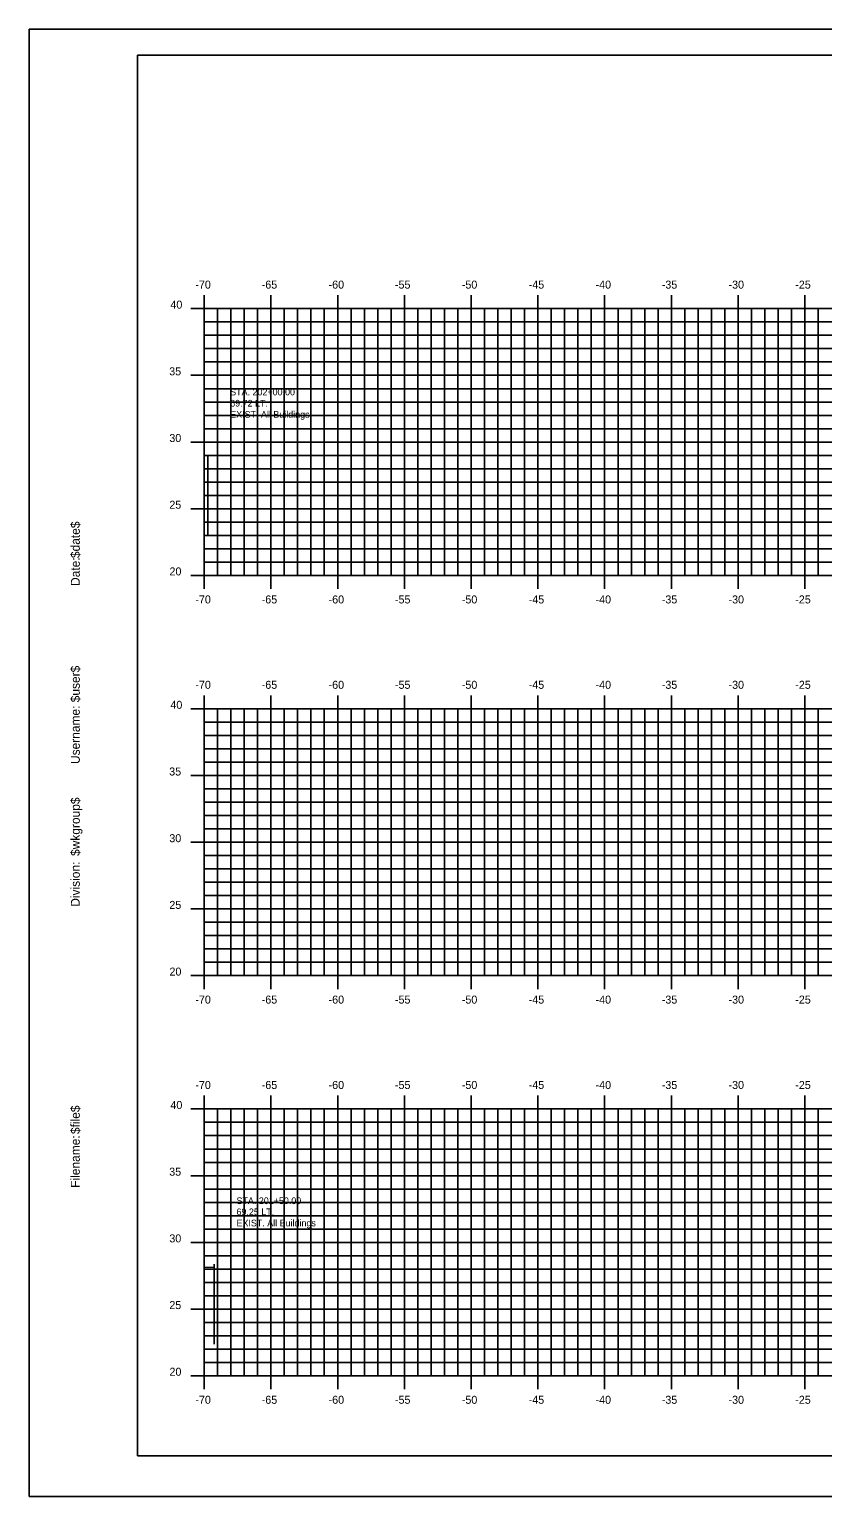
# Model space of a CAD drawing. Extents: x 1023905 to 1024075, y 394697 to 394807.
# Drawn here: x 1023904.6 to 1023964, y 394696.5 to 394806.5 of the extents above; entities that cross this region are included whole.
import ezdxf

# ---------------------------------------------------------------- set-up
doc = ezdxf.new("R2010")
doc.units = 0
for name, color, linetype in [('BORDER', 7, 'Continuous'), ('D_Text_Monospaced', 7, 'Continuous'), ('H_V ANNOTATION', 7, 'Continuous'), ('MAJOR', 7, 'Continuous'), ('MINOR', 7, 'Continuous'), ('PLOT BOUNDARY', 7, 'Continuous'), ('S_Roadway_Centerline', 7, 'Continuous'), ('S_Utilities_UG_Sanitary_Sewer', 7, 'Continuous')]:
    doc.layers.add(name, color=color, linetype=linetype)

msp = doc.modelspace()

# ---------------------------------------------------------------- linework, layer by layer
at = {"layer": 'BORDER'}
for p, q in [((1024072.67, 394804.61), (1023912.67, 394804.61)), ((1023912.67, 394804.61), (1023912.67, 394699.61)), ((1023912.67, 394699.61), (1024072.67, 394699.61))]:
    msp.add_line(p, q, dxfattribs=at)
at = {"layer": 'MAJOR'}
for p, q in [((1023916.66, 394785.61), (1023917.67, 394785.61)), ((1023917.67, 394786.61), (1023917.67, 394785.61)), ((1023917.67, 394785.61), (1024057.67, 394785.61)), ((1023917.67, 394765.61), (1023917.67, 394785.61)), ((1023922.67, 394786.61), (1023922.67, 394785.61)), ((1023922.67, 394765.61), (1023922.67, 394785.61)), ((1023927.67, 394786.61), (1023927.67, 394785.61)), ((1023927.67, 394765.61), (1023927.67, 394785.61)), ((1023932.67, 394786.61), (1023932.67, 394785.61)), ((1023932.67, 394765.61), (1023932.67, 394785.61)), ((1023937.67, 394786.61), (1023937.67, 394785.61)), ((1023937.67, 394765.61), (1023937.67, 394785.61)), ((1023942.67, 394786.61), (1023942.67, 394785.61)), ((1023942.67, 394765.61), (1023942.67, 394785.61)), ((1023947.67, 394786.61), (1023947.67, 394785.61)), ((1023947.67, 394765.61), (1023947.67, 394785.61)), ((1023952.67, 394786.61), (1023952.67, 394785.61)), ((1023952.67, 394765.61), (1023952.67, 394785.61)), ((1023957.67, 394786.61), (1023957.67, 394785.61)), ((1023957.67, 394765.61), (1023957.67, 394785.61)), ((1023962.67, 394786.61), (1023962.67, 394785.61)), ((1023962.67, 394765.61), (1023962.67, 394785.61)), ((1023916.66, 394780.61), (1023917.67, 394780.61)), ((1023917.67, 394780.61), (1024057.67, 394780.61)), ((1023916.66, 394775.61), (1023917.67, 394775.61)), ((1023917.67, 394775.61), (1024057.67, 394775.61)), ((1023916.66, 394770.61), (1023917.67, 394770.61)), ((1023917.67, 394770.61), (1024057.67, 394770.61)), ((1023916.66, 394765.61), (1023917.67, 394765.61)), ((1023917.67, 394765.61), (1024057.67, 394765.61)), ((1023917.67, 394764.6), (1023917.67, 394765.61)), ((1023922.67, 394764.6), (1023922.67, 394765.61)), ((1023927.67, 394764.6), (1023927.67, 394765.61)), ((1023932.67, 394764.6), (1023932.67, 394765.61)), ((1023937.67, 394764.6), (1023937.67, 394765.61)), ((1023942.67, 394764.6), (1023942.67, 394765.61)), ((1023947.67, 394764.6), (1023947.67, 394765.61)), ((1023952.67, 394764.6), (1023952.67, 394765.61)), ((1023957.67, 394764.6), (1023957.67, 394765.61)), ((1023962.67, 394764.6), (1023962.67, 394765.61)), ((1023917.67, 394756.61), (1023917.67, 394755.61)), ((1023922.67, 394756.61), (1023922.67, 394755.61)), ((1023927.67, 394756.61), (1023927.67, 394755.61)), ((1023932.67, 394756.61), (1023932.67, 394755.61)), ((1023937.67, 394756.61), (1023937.67, 394755.61)), ((1023942.67, 394756.61), (1023942.67, 394755.61)), ((1023947.67, 394756.61), (1023947.67, 394755.61)), ((1023952.67, 394756.61), (1023952.67, 394755.61)), ((1023957.67, 394756.61), (1023957.67, 394755.61)), ((1023962.67, 394756.61), (1023962.67, 394755.61)), ((1023916.66, 394755.61), (1023917.67, 394755.61)), ((1023917.67, 394755.61), (1024057.67, 394755.61)), ((1023917.67, 394735.61), (1023917.67, 394755.61)), ((1023922.67, 394735.61), (1023922.67, 394755.61)), ((1023927.67, 394735.61), (1023927.67, 394755.61)), ((1023932.67, 394735.61), (1023932.67, 394755.61)), ((1023937.67, 394735.61), (1023937.67, 394755.61)), ((1023942.67, 394735.61), (1023942.67, 394755.61)), ((1023947.67, 394735.61), (1023947.67, 394755.61)), ((1023952.67, 394735.61), (1023952.67, 394755.61)), ((1023957.67, 394735.61), (1023957.67, 394755.61)), ((1023962.67, 394735.61), (1023962.67, 394755.61)), ((1023916.66, 394750.61), (1023917.67, 394750.61)), ((1023917.67, 394750.61), (1024057.67, 394750.61)), ((1023916.66, 394745.61), (1023917.67, 394745.61)), ((1023917.67, 394745.61), (1024057.67, 394745.61)), ((1023916.66, 394740.61), (1023917.67, 394740.61)), ((1023917.67, 394740.61), (1024057.67, 394740.61)), ((1023916.66, 394735.61), (1023917.67, 394735.61)), ((1023917.67, 394735.61), (1024057.67, 394735.61)), ((1023917.67, 394734.6), (1023917.67, 394735.61)), ((1023922.67, 394734.6), (1023922.67, 394735.61)), ((1023927.67, 394734.6), (1023927.67, 394735.61)), ((1023932.67, 394734.6), (1023932.67, 394735.61)), ((1023937.67, 394734.6), (1023937.67, 394735.61)), ((1023942.67, 394734.6), (1023942.67, 394735.61)), ((1023947.67, 394734.6), (1023947.67, 394735.61)), ((1023952.67, 394734.6), (1023952.67, 394735.61)), ((1023957.67, 394734.6), (1023957.67, 394735.61)), ((1023962.67, 394734.6), (1023962.67, 394735.61)), ((1023917.67, 394726.61), (1023917.67, 394725.61)), ((1023922.67, 394726.61), (1023922.67, 394725.61)), ((1023927.67, 394726.61), (1023927.67, 394725.61)), ((1023932.67, 394726.61), (1023932.67, 394725.61)), ((1023937.67, 394726.61), (1023937.67, 394725.61)), ((1023942.67, 394726.61), (1023942.67, 394725.61)), ((1023947.67, 394726.61), (1023947.67, 394725.61)), ((1023952.67, 394726.61), (1023952.67, 394725.61)), ((1023957.67, 394726.61), (1023957.67, 394725.61)), ((1023962.67, 394726.61), (1023962.67, 394725.61)), ((1023916.66, 394725.61), (1023917.67, 394725.61)), ((1023917.67, 394725.61), (1024057.67, 394725.61)), ((1023917.67, 394705.61), (1023917.67, 394725.61)), ((1023922.67, 394705.61), (1023922.67, 394725.61)), ((1023927.67, 394705.61), (1023927.67, 394725.61)), ((1023932.67, 394705.61), (1023932.67, 394725.61)), ((1023937.67, 394705.61), (1023937.67, 394725.61)), ((1023942.67, 394705.61), (1023942.67, 394725.61)), ((1023947.67, 394705.61), (1023947.67, 394725.61)), ((1023952.67, 394705.61), (1023952.67, 394725.61)), ((1023957.67, 394705.61), (1023957.67, 394725.61)), ((1023962.67, 394705.61), (1023962.67, 394725.61)), ((1023916.66, 394720.61), (1023917.67, 394720.61)), ((1023917.67, 394720.61), (1024057.67, 394720.61)), ((1023916.66, 394715.61), (1023917.67, 394715.61)), ((1023917.67, 394715.61), (1024057.67, 394715.61)), ((1023916.66, 394710.61), (1023917.67, 394710.61)), ((1023917.67, 394710.61), (1024057.67, 394710.61)), ((1023916.66, 394705.61), (1023917.67, 394705.61)), ((1023917.67, 394705.61), (1024057.67, 394705.61)), ((1023917.67, 394704.6), (1023917.67, 394705.61)), ((1023922.67, 394704.6), (1023922.67, 394705.61)), ((1023927.67, 394704.6), (1023927.67, 394705.61)), ((1023932.67, 394704.6), (1023932.67, 394705.61)), ((1023937.67, 394704.6), (1023937.67, 394705.61)), ((1023942.67, 394704.6), (1023942.67, 394705.61)), ((1023947.67, 394704.6), (1023947.67, 394705.61)), ((1023952.67, 394704.6), (1023952.67, 394705.61)), ((1023957.67, 394704.6), (1023957.67, 394705.61)), ((1023962.67, 394704.6), (1023962.67, 394705.61))]:
    msp.add_line(p, q, dxfattribs=at)
at = {"layer": 'MINOR'}
for p, q in [((1023918.67, 394765.61), (1023918.67, 394785.61)), ((1023919.67, 394765.61), (1023919.67, 394785.61)), ((1023920.67, 394765.61), (1023920.67, 394785.61)), ((1023921.67, 394765.61), (1023921.67, 394785.61)), ((1023923.67, 394765.61), (1023923.67, 394785.61)), ((1023924.67, 394765.61), (1023924.67, 394785.61)), ((1023925.67, 394765.61), (1023925.67, 394785.61)), ((1023926.67, 394765.61), (1023926.67, 394785.61)), ((1023928.67, 394765.61), (1023928.67, 394785.61)), ((1023929.67, 394765.61), (1023929.67, 394785.61)), ((1023930.67, 394765.61), (1023930.67, 394785.61)), ((1023931.67, 394765.61), (1023931.67, 394785.61)), ((1023933.67, 394765.61), (1023933.67, 394785.61)), ((1023934.67, 394765.61), (1023934.67, 394785.61)), ((1023935.67, 394765.61), (1023935.67, 394785.61)), ((1023936.67, 394765.61), (1023936.67, 394785.61)), ((1023938.67, 394765.61), (1023938.67, 394785.61)), ((1023939.67, 394765.61), (1023939.67, 394785.61)), ((1023940.67, 394765.61), (1023940.67, 394785.61)), ((1023941.67, 394765.61), (1023941.67, 394785.61)), ((1023943.67, 394765.61), (1023943.67, 394785.61)), ((1023944.67, 394765.61), (1023944.67, 394785.61)), ((1023945.67, 394765.61), (1023945.67, 394785.61)), ((1023946.67, 394765.61), (1023946.67, 394785.61)), ((1023948.67, 394765.61), (1023948.67, 394785.61)), ((1023949.67, 394765.61), (1023949.67, 394785.61)), ((1023950.67, 394765.61), (1023950.67, 394785.61)), ((1023951.67, 394765.61), (1023951.67, 394785.61)), ((1023953.67, 394765.61), (1023953.67, 394785.61)), ((1023954.67, 394765.61), (1023954.67, 394785.61)), ((1023955.67, 394765.61), (1023955.67, 394785.61)), ((1023956.67, 394765.61), (1023956.67, 394785.61)), ((1023958.67, 394765.61), (1023958.67, 394785.61)), ((1023959.67, 394765.61), (1023959.67, 394785.61)), ((1023960.67, 394765.61), (1023960.67, 394785.61)), ((1023961.67, 394765.61), (1023961.67, 394785.61)), ((1023963.67, 394765.61), (1023963.67, 394785.61)), ((1023917.67, 394784.61), (1024057.67, 394784.61)), ((1023917.67, 394784.61), (1023918.67, 394784.61)), ((1023917.67, 394783.61), (1024057.67, 394783.61)), ((1023917.67, 394783.61), (1023918.67, 394783.61)), ((1023917.67, 394782.61), (1024057.67, 394782.61)), ((1023917.67, 394782.61), (1023918.67, 394782.61)), ((1023917.67, 394781.61), (1024057.67, 394781.61)), ((1023917.67, 394781.61), (1023918.67, 394781.61)), ((1023917.67, 394779.61), (1024057.67, 394779.61)), ((1023917.67, 394779.61), (1023918.67, 394779.61)), ((1023917.67, 394778.61), (1024057.67, 394778.61)), ((1023917.67, 394778.61), (1023918.67, 394778.61)), ((1023917.67, 394777.61), (1024057.67, 394777.61)), ((1023917.67, 394777.61), (1023918.67, 394777.61)), ((1023917.67, 394776.61), (1024057.67, 394776.61)), ((1023917.67, 394776.61), (1023918.67, 394776.61)), ((1023917.67, 394774.61), (1024057.67, 394774.61)), ((1023917.67, 394774.61), (1023918.67, 394774.61)), ((1023917.67, 394773.61), (1024057.67, 394773.61)), ((1023917.67, 394773.61), (1023918.67, 394773.61)), ((1023917.67, 394772.61), (1024057.67, 394772.61)), ((1023917.67, 394772.61), (1023918.67, 394772.61)), ((1023917.67, 394771.61), (1024057.67, 394771.61)), ((1023917.67, 394771.61), (1023918.67, 394771.61)), ((1023917.67, 394769.61), (1024057.67, 394769.61)), ((1023917.67, 394769.61), (1023918.67, 394769.61)), ((1023917.67, 394768.61), (1024057.67, 394768.61)), ((1023917.67, 394768.61), (1023918.67, 394768.61)), ((1023917.67, 394767.61), (1024057.67, 394767.61)), ((1023917.67, 394767.61), (1023918.67, 394767.61)), ((1023917.67, 394766.61), (1024057.67, 394766.61)), ((1023917.67, 394766.61), (1023918.67, 394766.61)), ((1023918.67, 394735.61), (1023918.67, 394755.61)), ((1023919.67, 394735.61), (1023919.67, 394755.61)), ((1023920.67, 394735.61), (1023920.67, 394755.61)), ((1023921.67, 394735.61), (1023921.67, 394755.61)), ((1023923.67, 394735.61), (1023923.67, 394755.61)), ((1023924.67, 394735.61), (1023924.67, 394755.61)), ((1023925.67, 394735.61), (1023925.67, 394755.61)), ((1023926.67, 394735.61), (1023926.67, 394755.61)), ((1023928.67, 394735.61), (1023928.67, 394755.61)), ((1023929.67, 394735.61), (1023929.67, 394755.61)), ((1023930.67, 394735.61), (1023930.67, 394755.61)), ((1023931.67, 394735.61), (1023931.67, 394755.61)), ((1023933.67, 394735.61), (1023933.67, 394755.61)), ((1023934.67, 394735.61), (1023934.67, 394755.61)), ((1023935.67, 394735.61), (1023935.67, 394755.61)), ((1023936.67, 394735.61), (1023936.67, 394755.61)), ((1023938.67, 394735.61), (1023938.67, 394755.61)), ((1023939.67, 394735.61), (1023939.67, 394755.61)), ((1023940.67, 394735.61), (1023940.67, 394755.61)), ((1023941.67, 394735.61), (1023941.67, 394755.61)), ((1023943.67, 394735.61), (1023943.67, 394755.61)), ((1023944.67, 394735.61), (1023944.67, 394755.61)), ((1023945.67, 394735.61), (1023945.67, 394755.61)), ((1023946.67, 394735.61), (1023946.67, 394755.61)), ((1023948.67, 394735.61), (1023948.67, 394755.61)), ((1023949.67, 394735.61), (1023949.67, 394755.61)), ((1023950.67, 394735.61), (1023950.67, 394755.61)), ((1023951.67, 394735.61), (1023951.67, 394755.61)), ((1023953.67, 394735.61), (1023953.67, 394755.61)), ((1023954.67, 394735.61), (1023954.67, 394755.61)), ((1023955.67, 394735.61), (1023955.67, 394755.61)), ((1023956.67, 394735.61), (1023956.67, 394755.61)), ((1023958.67, 394735.61), (1023958.67, 394755.61)), ((1023959.67, 394735.61), (1023959.67, 394755.61)), ((1023960.67, 394735.61), (1023960.67, 394755.61)), ((1023961.67, 394735.61), (1023961.67, 394755.61)), ((1023963.67, 394735.61), (1023963.67, 394755.61)), ((1023917.67, 394754.61), (1024057.67, 394754.61)), ((1023917.67, 394754.61), (1023918.67, 394754.61)), ((1023917.67, 394753.61), (1024057.67, 394753.61)), ((1023917.67, 394753.61), (1023918.67, 394753.61)), ((1023917.67, 394752.61), (1024057.67, 394752.61)), ((1023917.67, 394752.61), (1023918.67, 394752.61)), ((1023917.67, 394751.61), (1024057.67, 394751.61)), ((1023917.67, 394751.61), (1023918.67, 394751.61)), ((1023917.67, 394749.61), (1024057.67, 394749.61)), ((1023917.67, 394749.61), (1023918.67, 394749.61)), ((1023917.67, 394748.61), (1024057.67, 394748.61)), ((1023917.67, 394748.61), (1023918.67, 394748.61)), ((1023917.67, 394747.61), (1024057.67, 394747.61)), ((1023917.67, 394747.61), (1023918.67, 394747.61)), ((1023917.67, 394746.61), (1024057.67, 394746.61)), ((1023917.67, 394746.61), (1023918.67, 394746.61)), ((1023917.67, 394744.61), (1024057.67, 394744.61)), ((1023917.67, 394744.61), (1023918.67, 394744.61)), ((1023917.67, 394743.61), (1024057.67, 394743.61)), ((1023917.67, 394743.61), (1023918.67, 394743.61)), ((1023917.67, 394742.61), (1024057.67, 394742.61)), ((1023917.67, 394742.61), (1023918.67, 394742.61)), ((1023917.67, 394741.61), (1024057.67, 394741.61)), ((1023917.67, 394741.61), (1023918.67, 394741.61)), ((1023917.67, 394739.61), (1024057.67, 394739.61)), ((1023917.67, 394739.61), (1023918.67, 394739.61)), ((1023917.67, 394738.61), (1024057.67, 394738.61)), ((1023917.67, 394738.61), (1023918.67, 394738.61)), ((1023917.67, 394737.61), (1024057.67, 394737.61)), ((1023917.67, 394737.61), (1023918.67, 394737.61)), ((1023917.67, 394736.61), (1024057.67, 394736.61)), ((1023917.67, 394736.61), (1023918.67, 394736.61)), ((1023918.67, 394705.61), (1023918.67, 394725.61)), ((1023919.67, 394705.61), (1023919.67, 394725.61)), ((1023920.67, 394705.61), (1023920.67, 394725.61)), ((1023921.67, 394705.61), (1023921.67, 394725.61)), ((1023923.67, 394705.61), (1023923.67, 394725.61)), ((1023924.67, 394705.61), (1023924.67, 394725.61)), ((1023925.67, 394705.61), (1023925.67, 394725.61)), ((1023926.67, 394705.61), (1023926.67, 394725.61)), ((1023928.67, 394705.61), (1023928.67, 394725.61)), ((1023929.67, 394705.61), (1023929.67, 394725.61)), ((1023930.67, 394705.61), (1023930.67, 394725.61)), ((1023931.67, 394705.61), (1023931.67, 394725.61)), ((1023933.67, 394705.61), (1023933.67, 394725.61)), ((1023934.67, 394705.61), (1023934.67, 394725.61)), ((1023935.67, 394705.61), (1023935.67, 394725.61)), ((1023936.67, 394705.61), (1023936.67, 394725.61)), ((1023938.67, 394705.61), (1023938.67, 394725.61)), ((1023939.67, 394705.61), (1023939.67, 394725.61)), ((1023940.67, 394705.61), (1023940.67, 394725.61)), ((1023941.67, 394705.61), (1023941.67, 394725.61)), ((1023943.67, 394705.61), (1023943.67, 394725.61)), ((1023944.67, 394705.61), (1023944.67, 394725.61)), ((1023945.67, 394705.61), (1023945.67, 394725.61)), ((1023946.67, 394705.61), (1023946.67, 394725.61)), ((1023948.67, 394705.61), (1023948.67, 394725.61)), ((1023949.67, 394705.61), (1023949.67, 394725.61)), ((1023950.67, 394705.61), (1023950.67, 394725.61)), ((1023951.67, 394705.61), (1023951.67, 394725.61)), ((1023953.67, 394705.61), (1023953.67, 394725.61)), ((1023954.67, 394705.61), (1023954.67, 394725.61)), ((1023955.67, 394705.61), (1023955.67, 394725.61)), ((1023956.67, 394705.61), (1023956.67, 394725.61)), ((1023958.67, 394705.61), (1023958.67, 394725.61)), ((1023959.67, 394705.61), (1023959.67, 394725.61)), ((1023960.67, 394705.61), (1023960.67, 394725.61)), ((1023961.67, 394705.61), (1023961.67, 394725.61)), ((1023963.67, 394705.61), (1023963.67, 394725.61)), ((1023917.67, 394724.61), (1024057.67, 394724.61)), ((1023917.67, 394724.61), (1023918.67, 394724.61)), ((1023917.67, 394723.61), (1024057.67, 394723.61)), ((1023917.67, 394723.61), (1023918.67, 394723.61)), ((1023917.67, 394722.61), (1024057.67, 394722.61)), ((1023917.67, 394722.61), (1023918.67, 394722.61)), ((1023917.67, 394721.61), (1024057.67, 394721.61)), ((1023917.67, 394721.61), (1023918.67, 394721.61)), ((1023917.67, 394719.61), (1024057.67, 394719.61)), ((1023917.67, 394719.61), (1023918.67, 394719.61)), ((1023917.67, 394718.61), (1024057.67, 394718.61)), ((1023917.67, 394718.61), (1023918.67, 394718.61)), ((1023917.67, 394717.61), (1024057.67, 394717.61)), ((1023917.67, 394717.61), (1023918.67, 394717.61)), ((1023917.67, 394716.61), (1024057.67, 394716.61)), ((1023917.67, 394716.61), (1023918.67, 394716.61)), ((1023917.67, 394714.61), (1024057.67, 394714.61)), ((1023917.67, 394714.61), (1023918.67, 394714.61)), ((1023917.67, 394713.61), (1024057.67, 394713.61)), ((1023917.67, 394713.61), (1023918.67, 394713.61)), ((1023917.67, 394712.61), (1024057.67, 394712.61)), ((1023917.67, 394712.61), (1023918.67, 394712.61)), ((1023917.67, 394711.61), (1024057.67, 394711.61)), ((1023917.67, 394711.61), (1023918.67, 394711.61)), ((1023917.67, 394709.61), (1024057.67, 394709.61)), ((1023917.67, 394709.61), (1023918.67, 394709.61)), ((1023917.67, 394708.61), (1024057.67, 394708.61)), ((1023917.67, 394708.61), (1023918.67, 394708.61)), ((1023917.67, 394707.61), (1024057.67, 394707.61)), ((1023917.67, 394707.61), (1023918.67, 394707.61)), ((1023917.67, 394706.61), (1024057.67, 394706.61)), ((1023917.67, 394706.61), (1023918.67, 394706.61))]:
    msp.add_line(p, q, dxfattribs=at)
at = {"layer": 'PLOT BOUNDARY'}
msp.add_lwpolyline([(1023904.57, 394696.55), (1024074.57, 394696.55), (1024074.57, 394806.55), (1023904.57, 394806.55)], close=True, dxfattribs=at)
at = {"layer": 'S_Roadway_Centerline'}
msp.add_lwpolyline([(1023917.67, 394713.72), (1023918.42, 394713.75)], dxfattribs=at)
at = {"layer": 'S_Utilities_UG_Sanitary_Sewer'}
for p, q in [((1023917.95, 394774.61), (1023917.95, 394768.61)), ((1023918.42, 394713.98), (1023918.42, 394707.98))]:
    msp.add_line(p, q, dxfattribs=at)

# ---------------------------------------------------------------- texts
at = {"layer": 'BORDER'}
for s, p in [('$date$', (1023908.35, 394766.91)), ('Date:', (1023908.35, 394764.82)), ('$user$', (1023908.35, 394756.1)), ('Username:', (1023908.35, 394751.47)), ('$wkgroup$', (1023908.35, 394744.58)), ('Division:', (1023908.35, 394740.77)), ('$file$', (1023908.35, 394723.73)), ('Filename:', (1023908.35, 394719.7))]:
    msp.add_text(s, height=0.67, rotation=90, dxfattribs=at).set_placement(p)
at = {"layer": 'D_Text_Monospaced'}
for s, p in [('STA. 202+00.00', (1023919.62, 394779.11)), ('69.72 LT.', (1023919.62, 394778.27)), ('EXIST. All Buildings', (1023919.62, 394777.43)), ('STA. 201+50.00', (1023920.09, 394718.48)), ('69.25 LT.', (1023920.09, 394717.65)), ('EXIST. All Buildings', (1023920.09, 394716.81))]:
    msp.add_text(s, height=0.5, dxfattribs=at).set_placement(p)
at = {"layer": 'H_V ANNOTATION'}
for s, p in [('-70', (1023917.01, 394787.11)), ('-65', (1023921.98, 394787.11)), ('-60', (1023926.99, 394787.11)), ('-55', (1023931.96, 394787.11)), ('-50', (1023936.97, 394787.11)), ('-45', (1023941.98, 394787.11)), ('-40', (1023946.99, 394787.11)), ('-35', (1023951.95, 394787.11)), ('-30', (1023956.95, 394787.11)), ('-25', (1023961.95, 394787.11)), ('40', (1023915.14, 394785.61)), ('35', (1023915.05, 394780.61)), ('30', (1023915.06, 394775.61)), ('25', (1023915.06, 394770.61)), ('20', (1023915.07, 394765.61)), ('-70', (1023917.01, 394763.51)), ('-65', (1023921.98, 394763.51)), ('-60', (1023926.99, 394763.51)), ('-55', (1023931.96, 394763.51)), ('-50', (1023936.97, 394763.51)), ('-45', (1023941.98, 394763.51)), ('-40', (1023946.99, 394763.51)), ('-35', (1023951.95, 394763.51)), ('-30', (1023956.95, 394763.51)), ('-25', (1023961.95, 394763.51)), ('-70', (1023917.01, 394757.11)), ('-65', (1023921.98, 394757.11)), ('-60', (1023926.99, 394757.11)), ('-55', (1023931.96, 394757.11)), ('-50', (1023936.97, 394757.11)), ('-45', (1023941.98, 394757.11)), ('-40', (1023946.99, 394757.11)), ('-35', (1023951.95, 394757.11)), ('-30', (1023956.95, 394757.11)), ('-25', (1023961.95, 394757.11)), ('40', (1023915.14, 394755.61)), ('35', (1023915.05, 394750.61)), ('30', (1023915.06, 394745.61)), ('25', (1023915.06, 394740.61)), ('20', (1023915.07, 394735.61)), ('-70', (1023917.01, 394733.51)), ('-65', (1023921.98, 394733.51)), ('-60', (1023926.99, 394733.51)), ('-55', (1023931.96, 394733.51)), ('-50', (1023936.97, 394733.51)), ('-45', (1023941.98, 394733.51)), ('-40', (1023946.99, 394733.51)), ('-35', (1023951.95, 394733.51)), ('-30', (1023956.95, 394733.51)), ('-25', (1023961.95, 394733.51)), ('-70', (1023917.01, 394727.11)), ('-65', (1023921.98, 394727.11)), ('-60', (1023926.99, 394727.11)), ('-55', (1023931.96, 394727.11)), ('-50', (1023936.97, 394727.11)), ('-45', (1023941.98, 394727.11)), ('-40', (1023946.99, 394727.11)), ('-35', (1023951.95, 394727.11)), ('-30', (1023956.95, 394727.11)), ('-25', (1023961.95, 394727.11)), ('40', (1023915.14, 394725.61)), ('35', (1023915.05, 394720.61)), ('30', (1023915.06, 394715.61)), ('25', (1023915.06, 394710.61)), ('20', (1023915.07, 394705.61)), ('-70', (1023917.01, 394703.51)), ('-65', (1023921.98, 394703.51)), ('-60', (1023926.99, 394703.51)), ('-55', (1023931.96, 394703.51)), ('-50', (1023936.97, 394703.51)), ('-45', (1023941.98, 394703.51)), ('-40', (1023946.99, 394703.51)), ('-35', (1023951.95, 394703.51)), ('-30', (1023956.95, 394703.51)), ('-25', (1023961.95, 394703.51))]:
    msp.add_text(s, height=0.6, dxfattribs=at).set_placement(p)

doc.saveas('drawing.dxf')
